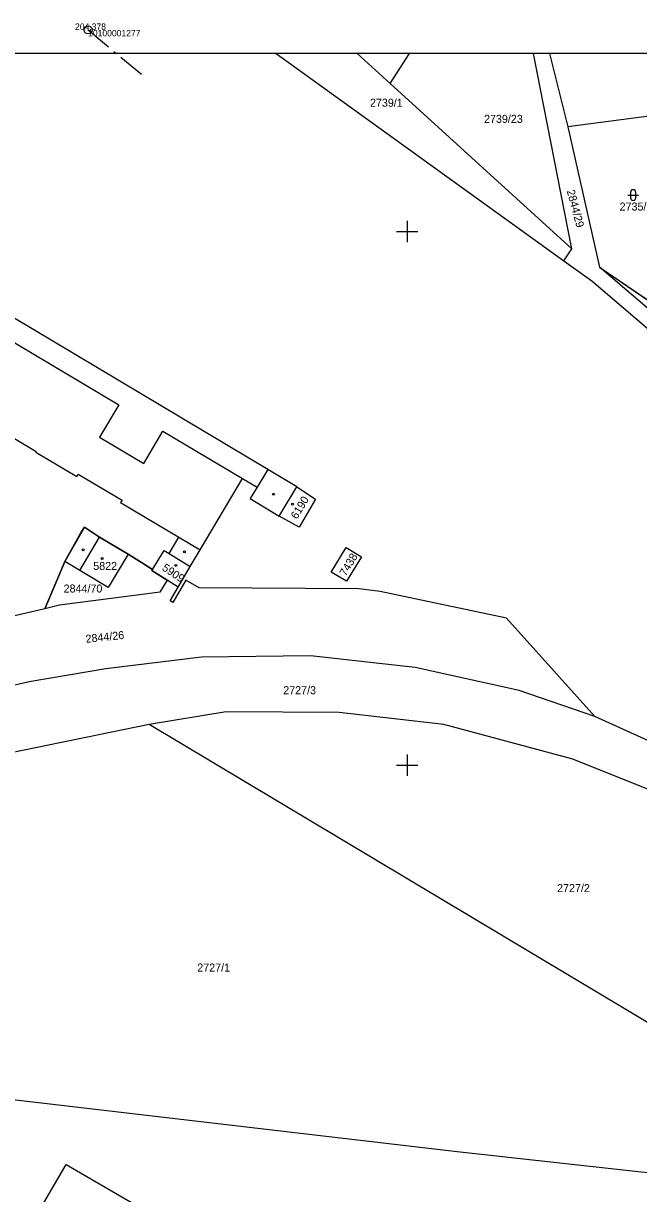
# Model space of a CAD drawing. Extents: x -800194 to -799078, y -1007177 to -1006597.
# Drawn here: x -800071.9 to -799956.6, y -1006980.2 to -1006761 of the extents above; entities that cross this region are included whole.
import ezdxf

# ---------------------------------------------------------------- set-up
doc = ezdxf.new("R2010")
doc.units = 0
for name, color, linetype in [('Legenda 1', 7, 'Continuous'), ('Ramove udaje', 7, 'Continuous'), ('Vrstva 53', 7, 'Continuous'), ('Vrstva 55', 7, 'Continuous'), ('Vrstva 56', 7, 'Continuous'), ('Vrstva 57', 7, 'Continuous'), ('Vrstva 58', 7, 'Continuous'), ('Vrstva 59', 7, 'Continuous'), ('Vrstva 60', 7, 'Continuous'), ('Vrstva 61', 7, 'Continuous'), ('Vrstva 63', 7, 'Continuous')]:
    doc.layers.add(name, color=color, linetype=linetype)

msp = doc.modelspace()

# ---------------------------------------------------------------- linework, layer by layer
at = {"layer": 'Legenda 1'}
msp.add_lwpolyline([(-800193.4, -1007176.65), (-799312.4, -1007176.65), (-799312.4, -1006766.65), (-800193.4, -1006766.65)], close=True, dxfattribs=at)
at = {"layer": 'Ramove udaje'}
for p, q in [((-800000, -1006798), (-800000, -1006802)), ((-800002, -1006800), (-800000, -1006800)), ((-800000, -1006800), (-799998, -1006800)), ((-800000, -1006898), (-800000, -1006902)), ((-800002, -1006900), (-800000, -1006900)), ((-800000, -1006900), (-799998, -1006900))]:
    msp.add_line(p, q, dxfattribs=at)
at = {"layer": 'Vrstva 53'}
for points in [[(-799973.31, -1006766.65), (-799969.88, -1006780.37), (-799963.94, -1006806.68), (-799940.15, -1006822.89)], [(-799954.76, -1006895.45), (-799964.79, -1006890.84), (-799981.37, -1006872.46), (-800005.05, -1006867.41), (-800009, -1006866.96), (-800038.94, -1006866.77), (-800041.43, -1006865.34), (-800043.88, -1006869.49), (-800044.4, -1006869.18), (-800042.89, -1006866.63), (-800044.93, -1006865.34), (-800047.78, -1006863.53), (-800047.67, -1006863.34), (-800049.72, -1006862.02), (-800052.27, -1006860.45), (-800057.6, -1006857.24), (-800060.43, -1006855.37), (-800064.08, -1006861.85), (-800067.83, -1006870.66), (-800083.75, -1006874.38)]]:
    msp.add_lwpolyline(points, dxfattribs=at)
at = {"layer": 'Vrstva 55'}
for p, q in [((-800024.53, -1006766.65), (-799970.63, -1006805.46)), ((-800003.16, -1006772.25), (-800009.31, -1006766.65)), ((-800003.16, -1006772.25), (-799999.51, -1006766.65)), ((-799969.12, -1006803.26), (-799976.33, -1006766.65)), ((-799973.31, -1006766.65), (-799969.88, -1006780.37)), ((-799969.12, -1006803.26), (-800003.16, -1006772.25)), ((-799953.68, -1006778.26), (-799969.88, -1006780.37)), ((-799969.88, -1006780.37), (-799963.94, -1006806.68)), ((-799970.63, -1006805.46), (-799969.12, -1006803.26)), ((-799970.63, -1006805.46), (-799965.36, -1006809.25)), ((-799963.94, -1006806.68), (-799940.15, -1006822.89)), ((-799965.36, -1006809.25), (-799930.99, -1006838.59)), ((-800023.97, -1006853.3), (-800020.66, -1006847.86)), ((-800042.78, -1006857.25), (-800038.76, -1006859.64)), ((-800042.89, -1006866.63), (-800044.93, -1006865.34)), ((-800067.83, -1006870.66), (-800083.75, -1006874.38)), ((-799905.8, -1006977.56), (-800048.34, -1006892.35))]:
    msp.add_line(p, q, dxfattribs=at)
for points in [[(-800020.66, -1006847.86), (-800026.06, -1006844.58), (-800089.97, -1006806.47), (-800092.01, -1006809.83), (-800100.11, -1006823.15)], [(-799922.45, -1006841.18), (-799927.36, -1006837.92), (-799963.94, -1006806.68)], [(-800077.33, -1006838.69), (-800076.4, -1006837.12), (-800069.48, -1006841.22), (-800069.56, -1006841.35), (-800061.89, -1006845.9), (-800061.61, -1006845.43), (-800053.39, -1006850.31), (-800053.68, -1006850.78), (-800042.78, -1006857.25)], [(-800038.76, -1006859.64), (-800030.81, -1006846.28), (-800028.08, -1006847.9), (-800029.37, -1006850.02), (-800023.97, -1006853.3)], [(-800020.66, -1006847.86), (-800017.12, -1006850.15), (-800020.18, -1006855.39), (-800023.97, -1006853.3)], [(-800064.08, -1006861.85), (-800061.02, -1006856.31), (-800060.43, -1006855.37), (-800057.6, -1006857.24), (-800052.27, -1006860.45)], [(-800047.67, -1006863.34), (-800045.49, -1006859.74), (-800044.59, -1006860.3), (-800042.78, -1006857.25)], [(-800052.27, -1006860.45), (-800055.96, -1006866.67), (-800061.32, -1006863.49), (-800064.08, -1006861.85)], [(-800052.27, -1006860.45), (-800049.72, -1006862.02), (-800047.67, -1006863.34)], [(-800042.89, -1006866.63), (-800040.61, -1006862.78), (-800038.76, -1006859.64)], [(-800008.55, -1006860.96), (-800011.33, -1006865.52), (-800014.19, -1006863.79), (-800011.42, -1006859.22), (-800008.55, -1006860.96)], [(-800067.83, -1006870.66), (-800064.25, -1006862.16), (-800064.08, -1006861.85)], [(-800047.67, -1006863.34), (-800047.78, -1006863.53), (-800044.93, -1006865.34)], [(-800044.93, -1006865.34), (-800046.33, -1006867.59), (-800049.13, -1006867.95), (-800065.09, -1006870.02), (-800067.83, -1006870.66)], [(-799964.79, -1006890.84), (-799981.37, -1006872.46), (-800005.05, -1006867.41), (-800009, -1006866.96), (-800038.94, -1006866.77), (-800041.43, -1006865.34), (-800043.88, -1006869.49), (-800044.4, -1006869.18), (-800042.89, -1006866.63)], [(-799964.79, -1006890.84), (-799979.01, -1006885.96), (-799998.45, -1006881.67), (-800018.08, -1006879.48), (-800038.51, -1006879.76), (-800056.43, -1006881.95), (-800070.76, -1006884.38), (-800080.47, -1006886.59), (-800089.79, -1006889.63), (-800088.91, -1006893.34), (-800105.12, -1006899.41), (-800124.67, -1006911.59), (-800137.62, -1006920.11), (-800154.3, -1006934.53), (-800165.04, -1006947.7)], [(-799901.69, -1006974.63), (-799900.54, -1006973.82), (-799898.31, -1006947.43), (-799904.63, -1006933.89), (-799915, -1006924.46), (-799932.22, -1006915.03), (-799953.17, -1006905.18), (-799968.93, -1006898.86), (-799993.08, -1006892.39), (-800012.71, -1006890.11), (-800033.89, -1006890), (-800048.34, -1006892.35)], [(-799839.73, -1006961.33), (-799877.87, -1006942.17), (-799936.47, -1006903.99), (-799954.76, -1006895.45), (-799964.79, -1006890.84)], [(-800048.34, -1006892.35), (-800095.49, -1006902.03), (-800108.2, -1006906.76), (-800120.56, -1006922.5)], [(-800126.38, -1006954.46), (-800114.82, -1006956.57), (-800087.75, -1006960.99), (-799990.59, -1006972.38), (-799910.85, -1006981.15)], [(-800069.59, -1006984.65), (-800063.85, -1006974.82), (-800037.33, -1006990.25), (-800033.78, -1006992.42), (-800023.89, -1006998.18), (-800020.27, -1007000.33), (-799995.43, -1007014.87), (-800001.26, -1007024.83), (-800026.05, -1007010.11), (-800029.71, -1007008.06), (-800039.6, -1007002.32), (-800043.23, -1007000.2), (-800069.59, -1006984.65)]]:
    msp.add_lwpolyline(points, dxfattribs=at)
at = {"layer": 'Vrstva 56'}
for p, q in [((-800092.01, -1006809.83), (-800054.01, -1006832.46)), ((-800054.01, -1006832.46), (-800057.61, -1006838.51)), ((-800057.61, -1006838.51), (-800049.33, -1006843.44)), ((-800049.33, -1006843.44), (-800045.73, -1006837.39)), ((-800045.73, -1006837.39), (-800030.81, -1006846.28)), ((-800026.06, -1006844.58), (-800028.08, -1006847.9)), ((-800061.32, -1006863.49), (-800057.6, -1006857.24)), ((-800044.59, -1006860.3), (-800040.61, -1006862.78))]:
    msp.add_line(p, q, dxfattribs=at)
at = {"layer": 'Vrstva 58'}
for p, q in [((-799958.14, -1006792.67), (-799958.14, -1006793.67)), ((-799957.14, -1006793.67), (-799957.14, -1006792.67)), ((-799958.64, -1006793.17), (-799956.64, -1006793.17))]:
    msp.add_line(p, q, dxfattribs=at)
for centre, start, end in [((-799957.64, -1006792.67), 0, 180), ((-799957.64, -1006793.67), 180, 359.9879)]:
    msp.add_arc(centre, 0.5, start, end, dxfattribs=at)
at = {"layer": 'Vrstva 59'}
for centre in [(-800025.01, -1006849.23), (-800021.44, -1006851.08), (-800060.68, -1006859.65), (-800041.71, -1006860), (-800057.13, -1006861.24), (-800043.33, -1006862.55)]:
    msp.add_circle(centre, 0.175, dxfattribs=at)
at = {"layer": 'Vrstva 60'}
msp.add_line((-800059.75, -1006762.22), (-800059.75, -1006762.22), dxfattribs=at)
msp.add_line((-800059.75, -1006762.22), (-800059.75, -1006762.22), dxfattribs=at)
at = {"layer": 'Vrstva 63'}
for p, q in [((-800059.71, -1006762.25), (-800059.79, -1006762.2)), ((-800059.75, -1006762.22), (-800055.9, -1006765.42)), ((-800054.9, -1006766.25), (-800054.6, -1006766.51)), ((-800053.6, -1006767.34), (-800049.75, -1006770.53))]:
    msp.add_line(p, q, dxfattribs=at)
msp.add_circle((-800059.75, -1006762.22), 0.756, dxfattribs=at)

# ---------------------------------------------------------------- texts
at = {"layer": 'Vrstva 57'}
for s, p in [('2739/1', (-800006.94, -1006776.62)), ('2739/23', (-799985.57, -1006779.64)), ('2735/1', (-799960.17, -1006796.07)), ('5822', (-800058.78, -1006863.4)), ('2844/70', (-800064.33, -1006867.63)), ('2727/3', (-800023.19, -1006886.68)), ('2727/2', (-799971.88, -1006923.75)), ('2727/1', (-800039.29, -1006938.64))]:
    msp.add_text(s, height=1.5, dxfattribs=at).set_placement(p)
for s, rotation, p in [('2844/29', 285, (-799970.09, -1006792.38)), ('6190', 59, (-800020.6, -1006854)), ('7438', 59, (-800011.47, -1006864.68)), ('5909', 326, (-800046.03, -1006863.34)), ('2844/26', 6, (-800060.13, -1006877.07))]:
    msp.add_text(s, height=1.5, rotation=rotation, dxfattribs=at).set_placement(p)
at = {"layer": 'Vrstva 60'}
msp.add_text('10100001277', height=1.2, dxfattribs=at).set_placement((-800059.75, -1006763.43))
msp.add_text('10100001277', height=1.2, dxfattribs=at).set_placement((-800059.75, -1006763.43))
at = {"layer": 'Vrstva 61'}
msp.add_text('204.378', height=1.2, dxfattribs=at).set_placement((-800062.2, -1006762.22))
msp.add_text('204.378', height=1.2, dxfattribs=at).set_placement((-800062.2, -1006762.22))

doc.saveas('drawing.dxf')
